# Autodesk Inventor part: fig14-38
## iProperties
Created: 2005-03
Part Number: fig14-38
Document SubType Name: Sheet Metal
Designer: CADCIM
Manufacturer: Standard
Standards Organization: Custom
Author: CADCIM
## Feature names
1. Plate1
2. Plate2
3. Bend1
